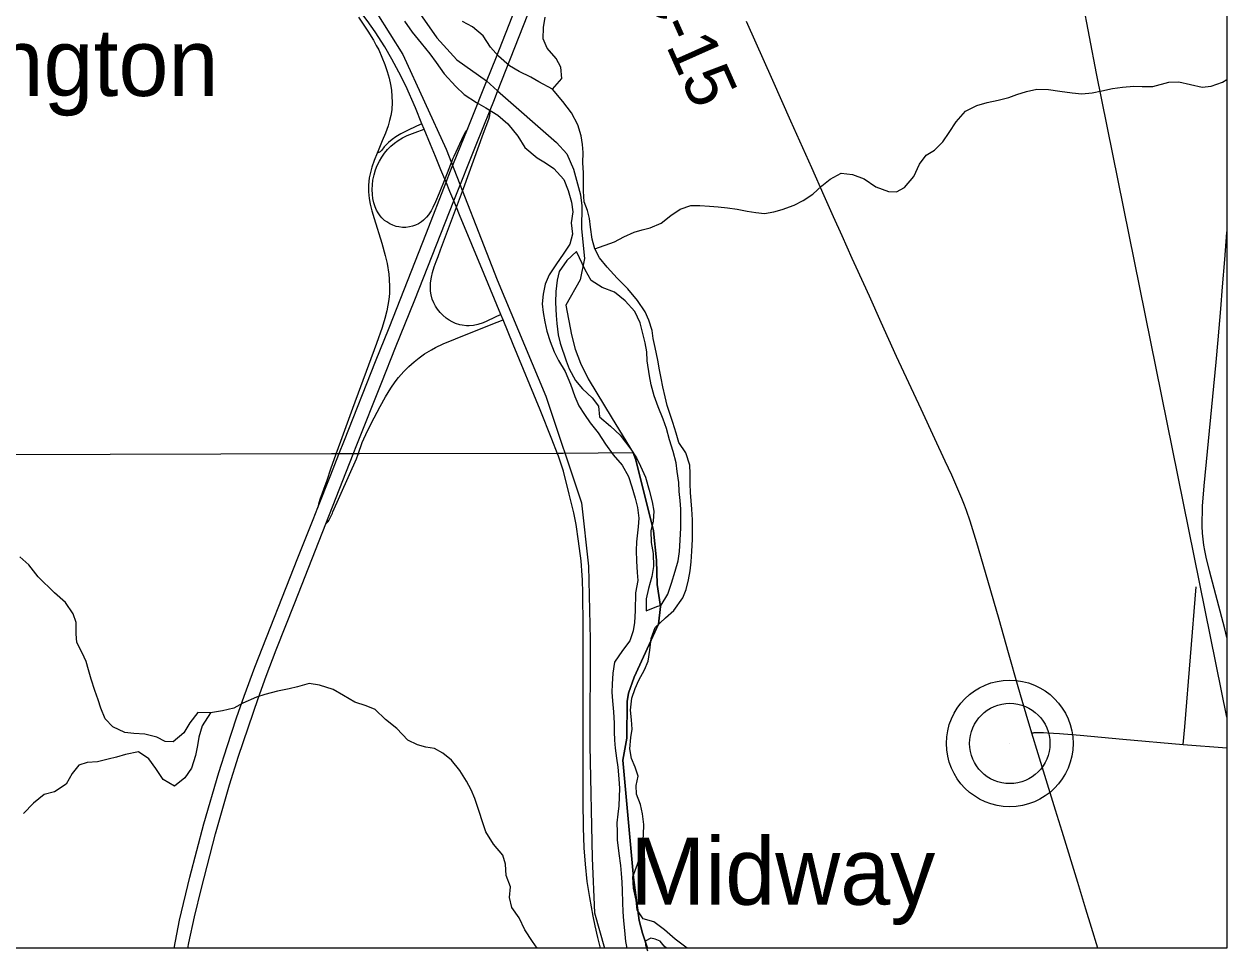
# Model space of a CAD drawing. Extents: x -87 to 2145, y -2128 to 440.
# Drawn here: x 192.89 to 230.18, y -1245.27 to -1216.53 of the extents above; entities that cross this region are included whole.
import ezdxf

# ---------------------------------------------------------------- set-up
doc = ezdxf.new("R2010")
doc.units = 0
for name, color, linetype in [('GM_X_County_Road', 7, 'Continuous'), ('GM_X_County_Road_Text', 7, 'Continuous'), ('GM_X_Interchange_Ramps', 7, 'Continuous'), ('GM_X_Interstate_Route', 7, 'Continuous'), ('GM_X_Major_River', 7, 'Continuous'), ('GM_X_Minor_River', 7, 'Continuous'), ('GM_X_Rail_Line', 7, 'Continuous'), ('GM_X_Township', 7, 'Continuous'), ('GM_X_Township_Road', 7, 'Continuous'), ('GM_X_Township_Text', 7, 'Continuous'), ('GM_X_Unincorporated', 7, 'Continuous'), ('GM_X_Unincorporated_Location', 7, 'Continuous'), ('GM_X_Unincorporated_Text', 7, 'Continuous'), ('SC_Scratch1', 7, 'Continuous')]:
    doc.layers.add(name, color=color, linetype=linetype)

msp = doc.modelspace()

# ---------------------------------------------------------------- linework, layer by layer
at = {"layer": 'GM_X_County_Road'}
for p, q in [((205.295, -1219.786), (205.228, -1219.624)), ((207.672, -1225.534), (207.154, -1224.283)), ((207.74, -1225.698), (207.672, -1225.534))]:
    msp.add_line(p, q, dxfattribs=at)
for points in [[(205.228, -1219.624), (205.025, -1219.13), (204.723, -1218.449), (204.514, -1218.019), (204.297, -1217.622), (204.071, -1217.231), (203.773, -1216.77), (203.533, -1216.42), (203.129, -1215.887), (202.755, -1215.415)], [(224.138, -1238.516), (223.963, -1237.93), (223.716, -1237.079), (223.41, -1236.023), (223.119, -1234.998), (222.694, -1233.533), (222.43, -1232.619), (222.222, -1231.946), (222.109, -1231.618), (222.046, -1231.445), (221.966, -1231.239), (221.651, -1230.519), (221.45, -1230.088), (221.123, -1229.393), (220.699, -1228.469), (219.938, -1226.834), (219.468, -1225.786), (219.1, -1224.963), (218.692, -1224.068), (218.568, -1223.8), (218.251, -1223.097), (217.988, -1222.509), (217.697, -1221.856), (217.312, -1220.986), (216.663, -1219.541), (216.102, -1218.278), (215.29, -1216.446)], [(207.154, -1224.283), (206.392, -1222.444), (206.294, -1222.207), (206.214, -1222.014), (206.094, -1221.725), (205.976, -1221.436), (205.936, -1221.337), (205.817, -1221.047), (205.647, -1220.638), (205.489, -1220.259), (205.295, -1219.786)], [(209.43, -1229.856), (209.255, -1229.401), (208.893, -1228.493), (208.058, -1226.466), (207.74, -1225.698)], [(210.201, -1233.758), (210.196, -1233.627), (210.159, -1233.171), (210.085, -1232.568), (210.007, -1232.052), (209.936, -1231.688), (209.796, -1231.104), (209.613, -1230.398), (209.459, -1229.933), (209.43, -1229.856)], [(210.761, -1245.188), (210.68, -1244.853), (210.594, -1244.488), (210.535, -1244.194), (210.427, -1243.611), (210.354, -1243.122), (210.295, -1242.581), (210.259, -1242.071), (210.235, -1241.446), (210.229, -1240.624), (210.23, -1238.312), (210.227, -1237.131), (210.224, -1236.409), (210.228, -1235.212), (210.218, -1234.181), (210.201, -1233.758)], [(226.182, -1245.188), (225.983, -1244.544), (225.809, -1243.978), (225.557, -1243.146), (225.074, -1241.569), (224.872, -1240.91), (224.622, -1240.1), (224.329, -1239.156), (224.138, -1238.516)]]:
    msp.add_lwpolyline(points, dxfattribs=at)
at = {"layer": 'GM_X_Interchange_Ramps'}
for points in [[(203.255, -1216.316), (203.548, -1216.751), (203.722, -1217.03), (203.811, -1217.19), (203.886, -1217.333), (203.988, -1217.556), (204.08, -1217.785), (204.15, -1218.003), (204.207, -1218.209), (204.25, -1218.401), (204.278, -1218.579), (204.296, -1218.775), (204.302, -1218.955), (204.288, -1219.185), (204.259, -1219.363), (204.222, -1219.522), (204.178, -1219.68), (204.095, -1219.912), (203.995, -1220.155), (203.869, -1220.458), (203.838, -1220.536), (203.747, -1220.762), (203.678, -1220.964), (203.621, -1221.17), (203.594, -1221.298), (203.567, -1221.525), (203.57, -1221.732), (203.593, -1221.933), (203.623, -1222.111), (203.673, -1222.319), (203.741, -1222.555), (203.979, -1223.323), (204.084, -1223.703), (204.145, -1223.958), (204.201, -1224.281), (204.215, -1224.444), (204.225, -1224.673), (204.224, -1224.779), (204.223, -1224.885), (204.203, -1225.066), (204.137, -1225.421), (204.077, -1225.658), (203.991, -1225.941), (203.818, -1226.437), (203.069, -1228.451), (202.699, -1229.473), (202.555, -1229.87)], [(207.672, -1225.534), (207.471, -1225.632), (207.242, -1225.744), (207.12, -1225.794), (206.964, -1225.844), (206.82, -1225.875), (206.689, -1225.886), (206.607, -1225.885), (206.477, -1225.87), (206.397, -1225.853), (206.272, -1225.812), (206.168, -1225.766), (206.067, -1225.71), (205.973, -1225.644), (205.873, -1225.559), (205.793, -1225.476), (205.71, -1225.374), (205.646, -1225.278), (205.594, -1225.176), (205.545, -1225.055), (205.513, -1224.928), (205.494, -1224.814), (205.491, -1224.668), (205.495, -1224.553), (205.524, -1224.375), (205.557, -1224.231), (205.61, -1224.058), (205.668, -1223.887), (205.727, -1223.733), (205.8, -1223.532), (206.294, -1222.207), (206.511, -1221.625), (207.139, -1219.913), (207.303, -1219.483), (207.329, -1219.369), (207.337, -1219.279), (207.34, -1219.203)], [(206.64, -1219.79), (206.603, -1219.834), (206.569, -1219.876), (206.513, -1219.982), (206.214, -1220.633), (206.188, -1220.699), (205.936, -1221.337), (205.765, -1221.768), (205.652, -1222.041), (205.568, -1222.222), (205.513, -1222.32), (205.428, -1222.444), (205.368, -1222.518), (205.274, -1222.611), (205.212, -1222.662), (205.115, -1222.723), (205.027, -1222.766), (204.934, -1222.799), (204.838, -1222.821), (204.724, -1222.833), (204.626, -1222.834), (204.512, -1222.82), (204.432, -1222.803), (204.323, -1222.766), (204.234, -1222.725), (204.135, -1222.666), (204.069, -1222.618), (203.985, -1222.54), (203.931, -1222.479), (203.865, -1222.385), (203.818, -1222.299), (203.773, -1222.193), (203.734, -1222.068), (203.707, -1221.94), (203.69, -1221.81), (203.683, -1221.663), (203.689, -1221.515), (203.708, -1221.369), (203.742, -1221.208), (203.789, -1221.051), (203.843, -1220.914), (203.908, -1220.782), (203.983, -1220.655), (204.068, -1220.534), (204.163, -1220.421), (204.267, -1220.317), (204.379, -1220.221), (204.485, -1220.143), (204.625, -1220.059), (204.773, -1219.989), (205.017, -1219.894), (205.295, -1219.786)], [(205.228, -1219.624), (205.062, -1219.699), (204.779, -1219.828), (204.576, -1219.931), (204.422, -1220.024), (204.302, -1220.109), (204.189, -1220.203), (204.119, -1220.272), (204.055, -1220.341), (203.981, -1220.441), (203.934, -1220.486), (203.887, -1220.515), (203.838, -1220.536)], [(203.254, -1229.87), (203.371, -1229.503), (203.537, -1229.147), (203.743, -1228.736), (203.929, -1228.389), (204.098, -1228.09), (204.261, -1227.824), (204.401, -1227.622), (204.5, -1227.492), (204.661, -1227.306), (204.824, -1227.144), (204.983, -1227.003), (205.137, -1226.881), (205.311, -1226.758), (205.52, -1226.629), (205.65, -1226.559), (205.886, -1226.445), (206.263, -1226.287), (207.374, -1225.844), (207.74, -1225.698)], [(202.555, -1229.87), (202.387, -1230.334), (202.273, -1230.682), (202.176, -1230.961), (202.062, -1231.274), (202.02, -1231.413), (201.997, -1231.521)], [(202.245, -1232.03), (202.282, -1231.993), (202.315, -1231.957), (202.335, -1231.927), (202.391, -1231.821), (202.45, -1231.698), (202.467, -1231.655), (203.195, -1230.006), (203.254, -1229.87)]]:
    msp.add_lwpolyline(points, dxfattribs=at)
at = {"layer": 'GM_X_Interstate_Route'}
msp.add_line((201.85, -1231.894), (201.997, -1231.521), dxfattribs=at)
for points in [[(206.64, -1219.79), (206.765, -1219.483), (207.231, -1218.308), (207.535, -1217.541), (208.699, -1214.579), (209.66, -1212.191), (210.6, -1209.83), (211.409, -1207.769), (211.655, -1207.142), (212.444, -1205.126), (213.364, -1202.809), (214.502, -1199.925), (215.124, -1198.354), (215.91, -1196.389), (216.366, -1195.229), (217.389, -1192.617), (218.201, -1190.576), (219.172, -1188.121), (219.989, -1186.08)], [(207.34, -1219.203), (207.454, -1218.924), (207.574, -1218.616), (208.507, -1216.232), (209.195, -1214.511), (209.828, -1212.892), (210.906, -1210.161), (211.644, -1208.29), (211.833, -1207.811), (212.71, -1205.601)], [(202.245, -1232.03), (203.096, -1229.87), (203.213, -1229.573), (203.982, -1227.637), (204.411, -1226.554), (205.002, -1225.076), (206.214, -1222.014), (206.904, -1220.273), (207.34, -1219.203)], [(201.997, -1231.521), (202.401, -1230.503), (202.652, -1229.87), (202.824, -1229.436), (203.79, -1226.996), (204.208, -1225.944), (205.372, -1223), (205.976, -1221.436), (206.115, -1221.077), (206.64, -1219.79)], [(197.544, -1245.188), (197.715, -1244.321), (198.028, -1242.98), (198.46, -1241.33), (198.929, -1239.742), (199.187, -1238.929), (199.479, -1238.041), (199.71, -1237.375), (200.043, -1236.467), (201.38, -1233.08), (201.85, -1231.894)], [(197.966, -1245.188), (198, -1245.017), (198.176, -1244.216), (198.388, -1243.321), (198.822, -1241.637), (199.258, -1240.123), (199.54, -1239.231), (200.147, -1237.444), (200.399, -1236.75), (200.709, -1235.938), (201.285, -1234.472), (202.245, -1232.03)]]:
    msp.add_lwpolyline(points, dxfattribs=at)
at = {"layer": 'GM_X_Major_River'}
for points in [[(204.681, -1216.434), (204.924, -1216.78), (205.206, -1217.117), (205.469, -1217.453), (205.663, -1217.718), (205.915, -1218.074), (206.277, -1218.462), (206.532, -1218.708), (206.917, -1218.957), (207.203, -1219.124), (207.579, -1219.353), (207.893, -1219.62), (208.204, -1220.008), (208.417, -1220.353), (208.8, -1220.672), (209.057, -1220.828), (209.313, -1221.004), (209.626, -1221.351), (209.758, -1221.695), (209.86, -1222.048), (209.903, -1222.349), (209.855, -1222.689), (209.897, -1223.04), (209.81, -1223.349), (209.623, -1223.635), (209.374, -1224), (209.166, -1224.306), (209.049, -1224.594), (208.982, -1224.903), (208.955, -1225.203), (208.989, -1225.474), (209.032, -1225.765), (209.095, -1226.057), (209.198, -1226.37), (209.331, -1226.693), (209.465, -1226.957), (209.667, -1227.302), (209.828, -1227.696), (209.97, -1228.08), (210.093, -1228.363), (210.267, -1228.637), (210.441, -1228.892), (210.685, -1229.208), (210.917, -1229.553), (211.16, -1229.889), (211.433, -1230.206), (211.635, -1230.561), (211.738, -1230.874), (211.84, -1231.227), (211.913, -1231.519), (211.955, -1231.851), (211.929, -1232.12), (211.878, -1232.58), (211.872, -1232.85), (211.874, -1233.181), (211.896, -1233.532), (211.92, -1233.783), (211.851, -1234.162), (211.838, -1234.723), (211.82, -1235.083), (211.773, -1235.343), (211.676, -1235.651), (211.448, -1235.956), (211.2, -1236.312), (211.141, -1236.661), (211.123, -1237.001), (211.118, -1237.251), (211.131, -1237.512), (211.164, -1237.853), (211.185, -1238.205), (211.189, -1238.475), (211.193, -1238.736), (211.217, -1238.987), (211.26, -1239.288), (211.304, -1239.57), (211.335, -1239.931), (211.348, -1240.232), (211.342, -1240.492), (211.326, -1240.772), (211.299, -1241.032), (211.273, -1241.302), (211.277, -1241.573), (211.281, -1241.823), (211.331, -1242.245), (211.382, -1242.617), (211.407, -1242.868), (211.42, -1243.139), (211.434, -1243.4)], [(212.096, -1241.671), (212.104, -1241.351), (212.061, -1241.019), (211.998, -1240.727), (211.875, -1240.414), (211.871, -1240.143), (211.928, -1239.854), (211.835, -1239.572), (211.721, -1239.298), (211.668, -1239.007), (211.706, -1238.657), (211.742, -1238.397), (211.719, -1238.106), (211.696, -1237.805), (211.734, -1237.435), (211.832, -1237.137), (211.948, -1236.879), (212.126, -1236.553), (212.242, -1236.285), (212.29, -1235.945), (212.329, -1235.586), (212.457, -1235.238), (212.775, -1234.944), (213.031, -1234.71), (213.31, -1234.325), (213.416, -1234.067), (213.494, -1233.758), (213.54, -1233.479), (213.577, -1233.209), (213.594, -1232.879), (213.613, -1232.509), (213.619, -1232.238), (213.617, -1231.898), (213.595, -1231.567), (213.571, -1231.316), (213.557, -1231.055), (213.543, -1230.784), (213.541, -1230.464), (213.527, -1230.203), (213.405, -1229.829), (213.192, -1229.504), (213.109, -1229.212), (213.006, -1228.889), (212.922, -1228.637), (212.829, -1228.354), (212.765, -1228.092), (212.692, -1227.78), (212.638, -1227.508), (212.594, -1227.247), (212.541, -1226.955), (212.46, -1226.563), (212.396, -1226.281), (212.362, -1226.03), (212.259, -1225.707), (212.145, -1225.454), (211.913, -1225.098), (211.611, -1224.741), (211.278, -1224.413), (210.965, -1224.065), (210.731, -1223.78), (210.588, -1223.496), (210.504, -1223.194), (210.453, -1222.832), (210.419, -1222.561), (210.355, -1222.309), (210.261, -1222.037), (210.239, -1221.706), (210.236, -1221.395), (210.232, -1221.145), (210.219, -1220.834), (210.226, -1220.513), (210.202, -1220.263), (210.168, -1219.991), (210.056, -1219.658), (209.864, -1219.283), (209.592, -1218.927), (209.27, -1218.549), (208.855, -1218.32), (208.598, -1218.174), (208.241, -1217.995), (207.945, -1217.829), (207.601, -1217.521), (207.357, -1217.245), (207.125, -1216.899), (206.791, -1216.611), (206.484, -1216.454)], [(210.014, -1223.584), (209.718, -1223.857), (209.479, -1224.203), (209.423, -1224.472), (209.374, -1224.821), (209.367, -1225.162), (209.387, -1225.563), (209.411, -1225.814), (209.453, -1226.165), (209.507, -1226.427), (209.695, -1226.972), (209.789, -1227.224), (209.991, -1227.58), (210.205, -1227.845), (210.5, -1228.122), (210.704, -1228.377), (210.736, -1228.708), (211.07, -1228.996), (211.374, -1229.273), (211.705, -1229.711), (211.879, -1229.976), (212.003, -1230.239), (212.155, -1230.583), (212.276, -1230.986), (212.368, -1231.349), (212.411, -1231.63), (212.394, -1231.941), (212.327, -1232.24), (212.329, -1232.6), (212.391, -1232.942), (212.401, -1233.353), (212.354, -1233.663), (212.255, -1234.031), (212.177, -1234.35), (212.179, -1234.721), (212.512, -1234.588), (212.644, -1234.551)], [(212.644, -1234.551), (212.852, -1234.205), (212.96, -1233.867), (213.079, -1233.489), (213.167, -1233.17), (213.214, -1232.88), (213.232, -1232.53), (213.251, -1232.15), (213.257, -1231.87), (213.254, -1231.569), (213.231, -1231.298), (213.197, -1231.027), (213.193, -1230.746), (213.141, -1230.405), (213.108, -1230.133), (213.016, -1229.781), (212.904, -1229.418), (212.812, -1229.075), (212.708, -1228.782), (212.547, -1228.398), (212.425, -1228.055), (212.333, -1227.712), (212.279, -1227.44), (212.21, -1226.968), (212.196, -1226.697), (212.142, -1226.416), (212.051, -1226.043), (211.987, -1225.791), (211.824, -1225.447), (211.522, -1225.11), (211.197, -1224.842), (210.81, -1224.693), (210.474, -1224.485), (210.282, -1224.15), (210.014, -1223.584)], [(213.446, -1245.188), (213.446, -1245.188), (213.082, -1244.909), (212.748, -1244.621), (212.413, -1244.373), (212.085, -1244.276), (211.901, -1243.991), (211.868, -1243.7), (211.787, -1243.327), (211.765, -1242.976), (211.914, -1242.579), (212.023, -1242.221), (212.07, -1241.931), (212.096, -1241.671)], [(211.434, -1243.4), (211.446, -1243.77), (211.459, -1244.061), (211.472, -1244.342), (211.506, -1244.633), (211.538, -1244.975), (211.575, -1245.188)], [(212.809, -1245.188), (212.736, -1245.122), (212.61, -1244.969), (212.461, -1244.905), (212.322, -1244.872), (212.149, -1244.969), (212.156, -1245.079), (212.222, -1245.271)]]:
    msp.add_lwpolyline(points, dxfattribs=at)
at = {"layer": 'GM_X_Minor_River'}
for points in [[(209.27, -1218.549), (209.559, -1218.215), (209.537, -1217.864), (209.393, -1217.6), (209.11, -1217.274), (208.986, -1216.991), (208.994, -1216.64), (209.042, -1216.311)], [(210.588, -1223.496), (211.194, -1223.279), (211.488, -1223.126), (211.802, -1222.982), (212.054, -1222.908), (212.306, -1222.843), (212.64, -1222.7), (212.946, -1222.467), (213.231, -1222.273), (213.564, -1222.16), (213.845, -1222.156), (214.145, -1222.173), (214.415, -1222.199), (214.695, -1222.225), (215.004, -1222.272), (215.314, -1222.329), (215.583, -1222.375), (215.843, -1222.401), (216.135, -1222.347), (216.397, -1222.283), (216.771, -1222.141), (217.045, -1221.997), (217.35, -1221.803), (217.626, -1221.549), (217.882, -1221.334), (218.226, -1221.152), (218.576, -1221.199), (218.934, -1221.327), (219.299, -1221.576), (219.686, -1221.725), (219.936, -1221.73), (220.19, -1221.596), (220.478, -1221.251), (220.647, -1220.874), (220.854, -1220.599), (221.118, -1220.444), (221.375, -1220.179), (221.572, -1219.893), (221.79, -1219.557), (222.078, -1219.233), (222.433, -1219.051), (222.746, -1218.957), (223.088, -1218.885), (223.421, -1218.802), (223.673, -1218.717), (223.966, -1218.624), (224.288, -1218.551), (224.649, -1218.559), (224.998, -1218.606), (225.387, -1218.665), (225.687, -1218.692), (226.009, -1218.659), (226.301, -1218.595), (226.633, -1218.522), (226.944, -1218.489), (227.296, -1218.457), (227.556, -1218.462), (227.887, -1218.46), (228.381, -1218.33), (228.692, -1218.317), (229.05, -1218.405), (229.419, -1218.483), (229.69, -1218.459), (230.044, -1218.327), (230.183, -1218.25)], [(198.669, -1237.892), (198.279, -1237.873), (198.031, -1238.198), (197.843, -1238.504), (197.516, -1238.787), (197.266, -1238.781), (197.008, -1238.645), (196.64, -1238.546), (196.29, -1238.528), (196.02, -1238.502), (195.643, -1238.323), (195.409, -1238.068), (195.276, -1237.744), (195.192, -1237.482), (195.089, -1237.199), (194.967, -1236.845), (194.884, -1236.553), (194.82, -1236.291), (194.696, -1236.028), (194.523, -1235.704), (194.509, -1235.433), (194.507, -1235.082), (194.413, -1234.82), (194.181, -1234.464), (193.838, -1234.165), (193.328, -1233.673), (193.036, -1233.296), (192.762, -1233.049)], [(208.796, -1245.188), (208.652, -1244.98), (208.42, -1244.614), (208.239, -1244.239), (208.015, -1243.924), (207.943, -1243.611), (207.97, -1243.281), (207.838, -1242.928), (207.817, -1242.577), (207.733, -1242.304), (207.44, -1241.957), (207.209, -1241.581), (207.115, -1241.299), (206.994, -1240.915), (206.862, -1240.542), (206.748, -1240.278), (206.605, -1240.005), (206.402, -1239.68), (206.139, -1239.353), (205.873, -1239.137), (205.616, -1238.991), (205.347, -1238.955), (205.088, -1238.879), (204.791, -1238.732), (204.449, -1238.373), (204.095, -1238.095), (203.781, -1237.787), (203.493, -1237.671), (203.145, -1237.552), (202.799, -1237.354), (202.473, -1237.167), (202.046, -1237.027), (201.726, -1236.979), (201.373, -1237.082), (201.111, -1237.146), (200.749, -1237.218), (200.356, -1237.319), (200.093, -1237.403), (199.678, -1237.584), (199.394, -1237.738), (199.041, -1237.83), (198.669, -1237.892), (198.409, -1238.286), (198.311, -1238.645), (198.265, -1238.904), (198.207, -1239.213), (198.078, -1239.601), (197.871, -1239.907), (197.554, -1240.16), (197.208, -1239.952), (196.976, -1239.616), (196.762, -1239.31), (196.437, -1239.093), (196.034, -1239.174), (195.762, -1239.258), (195.5, -1239.322), (195.167, -1239.404), (194.846, -1239.427), (194.594, -1239.511), (194.387, -1239.767), (194.199, -1240.103), (193.833, -1240.335), (193.511, -1240.418), (193.184, -1240.691), (192.876, -1241.004)]]:
    msp.add_lwpolyline(points, dxfattribs=at)
at = {"layer": 'GM_X_Rail_Line'}
for points in [[(230.183, -1238.018), (226.138, -1218.065), (224.184, -1207.821), (221.669, -1195.387), (217.209, -1173.171)], [(203.825, -1216.187), (204.633, -1217.472), (205.974, -1220.412), (207.558, -1224.461), (209.067, -1228.068), (210.175, -1231.372), (210.392, -1233.334), (210.445, -1235.615), (210.428, -1238.895), (210.502, -1242.393), (210.575, -1244.087), (210.891, -1245.188)]]:
    msp.add_lwpolyline(points, dxfattribs=at)
at = {"layer": 'GM_X_Township'}
msp.add_lwpolyline([(204.948, -1215.894), (205.692, -1216.956), (206.308, -1217.635), (207.225, -1218.294), (207.568, -1218.602), (209.401, -1220.2), (209.715, -1220.556), (209.926, -1221.024), (210.147, -1221.827), (210.181, -1222.167), (210.172, -1222.874), (210.271, -1223.796), (210.127, -1224.456), (209.689, -1225.241), (209.867, -1226.162), (209.978, -1226.61), (210.139, -1227.049), (210.379, -1227.525), (211.125, -1228.757), (211.776, -1229.826), (209.606, -1229.841), (209.424, -1229.842), (203.291, -1229.855), (203.248, -1229.856), (203.09, -1229.856), (202.646, -1229.856), (202.549, -1229.856), (202.426, -1229.856), (188.686, -1229.898)], dxfattribs=at)
at = {"layer": 'GM_X_Township_Road'}
msp.add_line((228.83, -1238.872), (230.183, -1238.974), dxfattribs=at)
for points in [[(230.183, -1235.554), (230.114, -1235.286), (229.787, -1234.029), (229.643, -1233.479), (229.54, -1233.061), (229.493, -1232.851), (229.466, -1232.692), (229.444, -1232.504), (229.427, -1232.316), (229.413, -1232.102), (229.43, -1231.48), (229.478, -1230.845), (229.854, -1227.009), (229.91, -1226.322), (229.993, -1225.359), (230.05, -1224.675), (230.115, -1223.826), (230.182, -1222.993), (230.183, -1222.972)], [(228.83, -1238.872), (228.883, -1238.318), (229.229, -1233.984)], [(224.138, -1238.516), (224.164, -1238.51), (224.187, -1238.505), (224.209, -1238.501), (224.226, -1238.498), (224.243, -1238.496), (224.263, -1238.494), (224.285, -1238.494), (224.337, -1238.494), (224.494, -1238.499), (224.619, -1238.505), (224.992, -1238.526), (225.629, -1238.583), (226.956, -1238.701), (228.83, -1238.872)]]:
    msp.add_lwpolyline(points, dxfattribs=at)
at = {"layer": 'GM_X_Township_Text'}
for points in [[(204.948, -1215.894), (205.692, -1216.956), (206.308, -1217.635), (207.225, -1218.294), (207.568, -1218.602), (209.401, -1220.2), (209.715, -1220.556), (209.926, -1221.024), (210.147, -1221.827), (210.181, -1222.167), (210.172, -1222.874), (210.271, -1223.796), (210.127, -1224.456), (209.689, -1225.241), (209.867, -1226.162), (209.978, -1226.61), (210.139, -1227.049), (210.379, -1227.525), (211.125, -1228.757), (211.776, -1229.826), (211.861, -1230.045), (212.403, -1232.241), (212.495, -1233.155), (212.518, -1233.904), (212.619, -1234.592), (212.556, -1235.139), (211.803, -1236.782), (211.626, -1237.273), (211.592, -1237.531), (211.582, -1238.677), (211.456, -1239.357), (211.786, -1242.993), (211.959, -1244.325), (212.061, -1244.721), (212.219, -1245.188)], [(212.219, -1245.188), (212.061, -1244.721), (211.959, -1244.325), (211.786, -1242.993), (211.456, -1239.357), (211.582, -1238.677), (211.592, -1237.531), (211.626, -1237.273), (211.803, -1236.782), (212.556, -1235.139), (212.619, -1234.592), (212.518, -1233.904), (212.495, -1233.155), (212.403, -1232.241), (211.861, -1230.045), (211.776, -1229.826), (209.606, -1229.841), (209.424, -1229.842), (203.291, -1229.855), (203.248, -1229.856), (203.09, -1229.856), (202.646, -1229.856), (202.549, -1229.856), (202.426, -1229.856), (188.686, -1229.898)]]:
    msp.add_lwpolyline(points, dxfattribs=at)
at = {"layer": 'GM_X_Unincorporated'}
for radius in [1.964, 1.245]:
    msp.add_circle((223.451, -1238.837), radius, dxfattribs=at)
at = {"layer": 'GM_X_Unincorporated_Location'}
msp.add_line((223.451, -1238.837), (223.451, -1238.837), dxfattribs=at)
at = {"layer": 'SC_Scratch1'}
msp.add_lwpolyline([(-21.617, -825.188), (230.183, -825.188), (230.183, -1245.188), (-21.617, -1245.188)], close=True, dxfattribs=at)

# ---------------------------------------------------------------- texts
at = {"layer": 'GM_X_County_Road_Text'}
msp.add_text('C-15', height=1.5, rotation=294.0203, dxfattribs=at).set_placement((211.921, -1215.264))
at = {"layer": 'GM_X_Unincorporated_Text'}
for s, p in [('Farrington', (186.212, -1218.758)), ('Midway', (211.688, -1243.838))]:
    msp.add_text(s, height=2.085, rotation=0, dxfattribs=at).set_placement(p)

doc.saveas('drawing.dxf')
